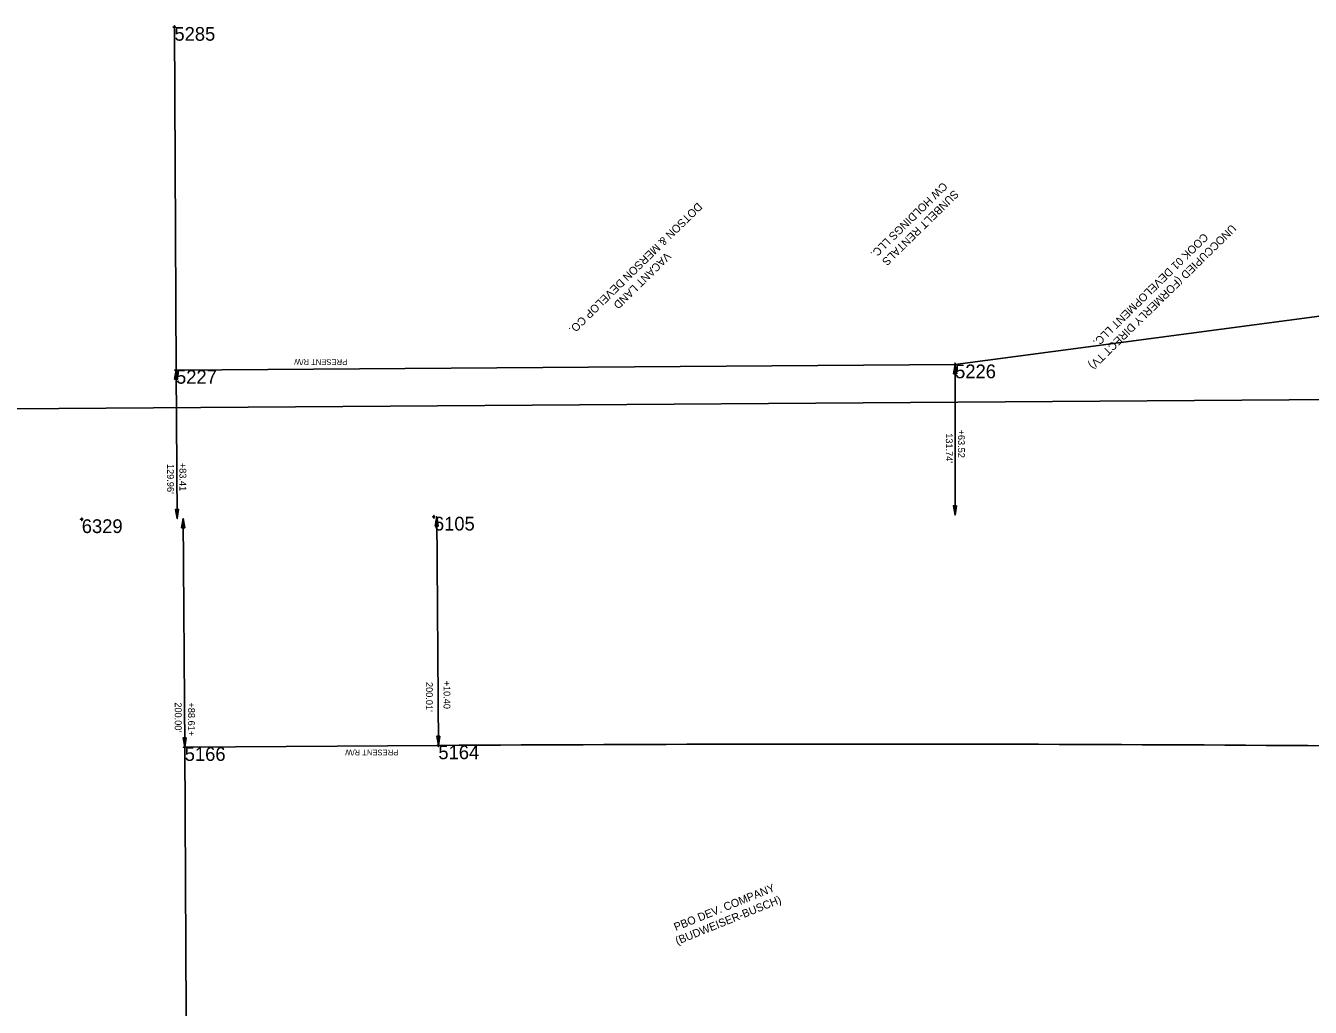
# Model space of a CAD drawing. Extents: x 2145146 to 2158053, y 137507 to 150829.
# Drawn here: x 2153955 to 2155078, y 142495 to 143354 of the extents above; entities that cross this region are included whole.
import ezdxf

# ---------------------------------------------------------------- set-up
doc = ezdxf.new("R2010")
doc.units = 0
for name, color, linetype in [('ALIGN_Cogo Points', 7, 'Continuous'), ('ALIGN_ROW Dimension', 7, 'Continuous'), ('ALIGN_ROW Line', 7, 'Continuous'), ('ALIGN_ROW Text', 7, 'Continuous'), ('PLSS_Property Line', 7, 'Continuous'), ('PLSS_Section Line', 7, 'Continuous'), ('PLSS_Text_TURNED OFF', 7, 'Continuous')]:
    doc.layers.add(name, color=color, linetype=linetype)

# ---------------------------------------------------------------- blocks, each defined once
blk = doc.blocks.new('Arrowhd')
at = {"layer": 'PLSS_Property Line'}
blk.add_lwpolyline([(0.125, -0.021), (0.125, 0.021), (0, 0)], close=True, dxfattribs=at)

msp = doc.modelspace()

# ---------------------------------------------------------------- linework, layer by layer
at = {"layer": 'ALIGN_Cogo Points'}
for points in [[(2154084.9, 143352.9), (2154084.9, 143354.1), (2154084.9, 143352.9), (2154083.7, 143352.9), (2154084.9, 143352.9), (2154084.9, 143351.7), (2154084.9, 143352.9), (2154086.1, 143352.9)], [(2154086.3, 143052.9), (2154086.3, 143054.1), (2154086.3, 143052.9), (2154085.1, 143052.9), (2154086.3, 143052.9), (2154086.3, 143051.7), (2154086.3, 143052.9), (2154087.5, 143052.9)], [(2154767.5, 143057.7), (2154767.5, 143058.9), (2154767.5, 143057.7), (2154766.3, 143057.7), (2154767.5, 143057.7), (2154767.5, 143056.5), (2154767.5, 143057.7), (2154768.7, 143057.7)], [(2154003.9, 142922.3), (2154003.9, 142923.5), (2154003.9, 142922.3), (2154002.7, 142922.3), (2154003.9, 142922.3), (2154003.9, 142921.1), (2154003.9, 142922.3), (2154005.1, 142922.3)], [(2154311.8, 142924.5), (2154311.8, 142925.7), (2154311.8, 142924.5), (2154310.6, 142924.5), (2154311.8, 142924.5), (2154311.8, 142923.3), (2154311.8, 142924.5), (2154313, 142924.5)], [(2154315.7, 142724.5), (2154315.7, 142725.7), (2154315.7, 142724.5), (2154314.5, 142724.5), (2154315.7, 142724.5), (2154315.7, 142723.3), (2154315.7, 142724.5), (2154316.9, 142724.5)], [(2154093.9, 142723), (2154093.9, 142724.2), (2154093.9, 142723), (2154092.7, 142723), (2154093.9, 142723), (2154093.9, 142721.8), (2154093.9, 142723), (2154095.1, 142723)]]:
    msp.add_lwpolyline(points, dxfattribs=at)
at = {"layer": 'ALIGN_ROW Dimension'}
for points in [[(2154086.3, 143052.9), (2154087.3, 142922.9)], [(2154767.5, 143057.7), (2154767.4, 142926)], [(2154093.9, 142723), (2154092.5, 142923)], [(2154315.7, 142724.5), (2154314.3, 142924.5)]]:
    msp.add_lwpolyline(points, dxfattribs=at)
at = {"layer": 'ALIGN_ROW Line'}
for points in [[(2154086.3, 143052.9), (2154084.9, 143352.9)], [(2154767.5, 143057.7), (2155580.5, 143165.7)], [(2154086.3, 143052.9), (2154767.5, 143057.7)], [(2154100.3, 141439.9), (2154093.9, 142723), (2154315.7, 142724.5)]]:
    msp.add_lwpolyline(points, dxfattribs=at)
msp.add_arc((2154686, 85629.9), 57095.8, 89.20928, 90.37163, dxfattribs=at)
at = {"layer": 'PLSS_Section Line'}
msp.add_lwpolyline([(2153570, 143016.2), (2156217.7, 143035)], dxfattribs=at)

# ---------------------------------------------------------------- block references
at = {"layer": 'ALIGN_ROW Dimension', "xscale": 65}
for p, yscale, rotation in [((2154086.3, 143052.9), 65.00000000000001, -89.5901679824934), ((2154767.5, 143057.7), 65, -90.04570132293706), ((2154087.3, 142922.9), 65, 90.40983201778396), ((2154767.4, 142926), 65, 89.95429867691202), ((2154092.5, 142923), 65, -89.58769416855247), ((2154314.2, 142924.5), 65, -89.59163428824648), ((2154093.9, 142723), 65, 90.40983201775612), ((2154315.7, 142724.5), 65, 90.44813381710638)]:
    msp.add_blockref('Arrowhd', p, dxfattribs=dict(at, yscale=yscale, rotation=rotation))

# ---------------------------------------------------------------- texts
at = {"layer": 'ALIGN_Cogo Points'}
for s, p in [('5285', (2154084.9, 143340.9)), ('5227', (2154086.3, 143040.9)), ('5226', (2154767.5, 143045.7)), ('6329', (2154003.9, 142910.3)), ('6105', (2154311.8, 142912.5)), ('5166', (2154093.9, 142711)), ('5164', (2154315.7, 142712.5))]:
    msp.add_text(s, height=12, dxfattribs=at).set_placement(p)
at = {"layer": 'ALIGN_ROW Dimension'}
for s, p in [("131.74'", (2154759.4, 142997.6)), ('+63.52', (2154770, 143000.8)), ("129.96'", (2154078.5, 142970.7)), ('+83.41', (2154089.3, 142971.7)), ("200.01'", (2154304.8, 142780)), ('+10.40', (2154320.2, 142781.2)), ("200.00'", (2154085.2, 142762.2)), ('+88.61+', (2154096.8, 142762.1))]:
    msp.add_text(s, height=6, rotation=270, dxfattribs=at).set_placement(p)
at = {"layer": 'ALIGN_ROW Text'}
for p in [(2154236, 143062.3), (2154280.7, 142720.8)]:
    msp.add_text('PRESENT R/W', height=5, rotation=179.8268, dxfattribs=at).set_placement(p)
at = {"layer": 'PLSS_Text_TURNED OFF'}
for s, rotation, p in [('CW HOLDINGS LLC.', 224.4738, (2154756.7, 143217.7)), ('SUNBELT RENTALS', 224.4738, (2154766.5, 143210.9)), ('DOTSON & MERSON DEVELOP CO.', 224.4738, (2154542.3, 143199.9)), ('UNOCCUPIED (FORMERLY DIRECT TV)', 224.4738, (2155009.1, 143180.8)), ('COOK 01 DEVELOPMENT LLC.', 224.4738, (2154984.7, 143173.2)), ('VACANT LAND', 224.4738, (2154514.9, 143156.5)), ('PBO DEV. COMPANY', 22, (2154523.3, 142562.1)), ('(BUDWEISER-BUSCH)', 22, (2154524.6, 142550))]:
    msp.add_text(s, height=7, rotation=rotation, dxfattribs=at).set_placement(p)

doc.saveas('drawing.dxf')
